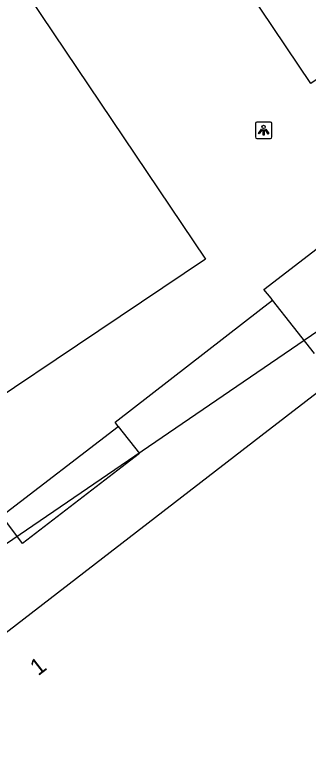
# Model space of a CAD drawing. Extents: x 161087 to 161922, y 382574 to 383873.
# Drawn here: x 161485.18 to 161502.86, y 382895.21 to 382939.12 of the extents above; entities that cross this region are included whole.
import ezdxf

# ---------------------------------------------------------------- set-up
doc = ezdxf.new("R2010")
doc.units = 0
for name, color, linetype in [('IMGEO_Lichtpunt', 7, 'Continuous'), ('IMGEO_Pand', 7, 'Continuous'), ('IMGEO_Pand_nummerreeks', 7, 'Continuous'), ('IMGEO_Pand_overbouw', 7, 'Continuous'), ('IMGEO_Voetgangersgebied_open', 7, 'Continuous'), ('IMGEO_Voetpad_op_trap', 7, 'Continuous')]:
    doc.layers.add(name, color=color, linetype=linetype)

msp = doc.modelspace()

# ---------------------------------------------------------------- linework, layer by layer
at = {"layer": 'IMGEO_Lichtpunt'}
for p, q in [((161499.665, 382932.554), (161499.665, 382931.747)), ((161499.665, 382932.554), (161499.665, 382931.747)), ((161500.567, 382932.649), (161499.759, 382932.649)), ((161500.567, 382932.649), (161499.759, 382932.649)), ((161500.661, 382931.747), (161500.661, 382932.554)), ((161500.661, 382931.747), (161500.661, 382932.554)), ((161499.759, 382931.653), (161500.567, 382931.653)), ((161499.759, 382931.653), (161500.567, 382931.653))]:
    msp.add_line(p, q, dxfattribs=at)
for points in [[(161500.039, 382932.218), (161500.078, 382932.19), (161499.89, 382931.928), (161499.852, 382931.955), (161500.039, 382932.218)], [(161500.141, 382932.17), (161500.188, 382932.17), (161500.188, 382931.848), (161500.141, 382931.848), (161500.141, 382932.17)], [(161500.251, 382932.19), (161500.289, 382932.217), (161500.476, 382931.955), (161500.437, 382931.927), (161500.251, 382932.19)]]:
    msp.add_lwpolyline(points, dxfattribs=at)
msp.add_circle((161500.164, 382932.352), 0.0994, dxfattribs=at)
for centre, start, end in [((161499.759, 382932.554), 90, 180), ((161499.759, 382932.554), 90, 180), ((161500.567, 382932.554), 0, 90), ((161500.567, 382932.554), 0, 90), ((161499.759, 382931.747), 180, 270), ((161499.759, 382931.747), 180, 270), ((161500.567, 382931.747), 270, 0), ((161500.567, 382931.747), 270, 360)]:
    msp.add_arc(centre, 0.0946, start, end, dxfattribs=at)
at = {"layer": 'IMGEO_Pand'}
msp.add_lwpolyline([(161496.266, 382848.732), (161495.302, 382847.988), (161473.698, 382875.969), (161465.241, 382886.911), (161469.189, 382889.988), (161468.666, 382890.646), (161480.418, 382899.706), (161480.962, 382899.05), (161500, 382913.739), (161504.189, 382916.971), (161504.422, 382917.152)], dxfattribs=at)
at = {"layer": 'IMGEO_Pand_overbouw'}
msp.add_lwpolyline([(161492.605, 382965.232), (161429.792, 382922.791), (161453.212, 382885.739), (161522.217, 382932.918), (161506.849, 382955.782), (161501.427, 382952.07)], close=True, dxfattribs=at)
at = {"layer": 'IMGEO_Voetgangersgebied_open'}
for points in [[(161496.661, 382924.391), (161455.681, 382896.825), (161428.165, 382937.798), (161469.152, 382965.318), (161496.661, 382924.391)], [(161512.58, 382941.413), (161503.013, 382934.968), (161500, 382939.449), (161485.192, 382961.474), (161491.048, 382965.377)], [(161491.418, 382914.303), (161491.228, 382914.562), (161500, 382921.365), (161500.704, 382921.911)]]:
    msp.add_lwpolyline(points, dxfattribs=at)
at = {"layer": 'IMGEO_Voetpad_op_trap'}
for points in [[(161500.704, 382921.911), (161500.61, 382922.031), (161500.185, 382922.554), (161507.902, 382928.506), (161510.463, 382930.552), (161510.935, 382929.942)], [(161503.226, 382918.699), (161500.704, 382921.911)], [(161484.399, 382908.913), (161491.418, 382914.303)], [(161491.418, 382914.303), (161492.692, 382912.683), (161485.65, 382907.256), (161484.399, 382908.913)]]:
    msp.add_lwpolyline(points, dxfattribs=at)

# ---------------------------------------------------------------- texts
at = {"layer": 'IMGEO_Pand_nummerreeks'}
msp.add_text('1', height=1, rotation=37.6605, dxfattribs=at).set_placement((161486.592, 382899.247))

doc.saveas('drawing.dxf')
